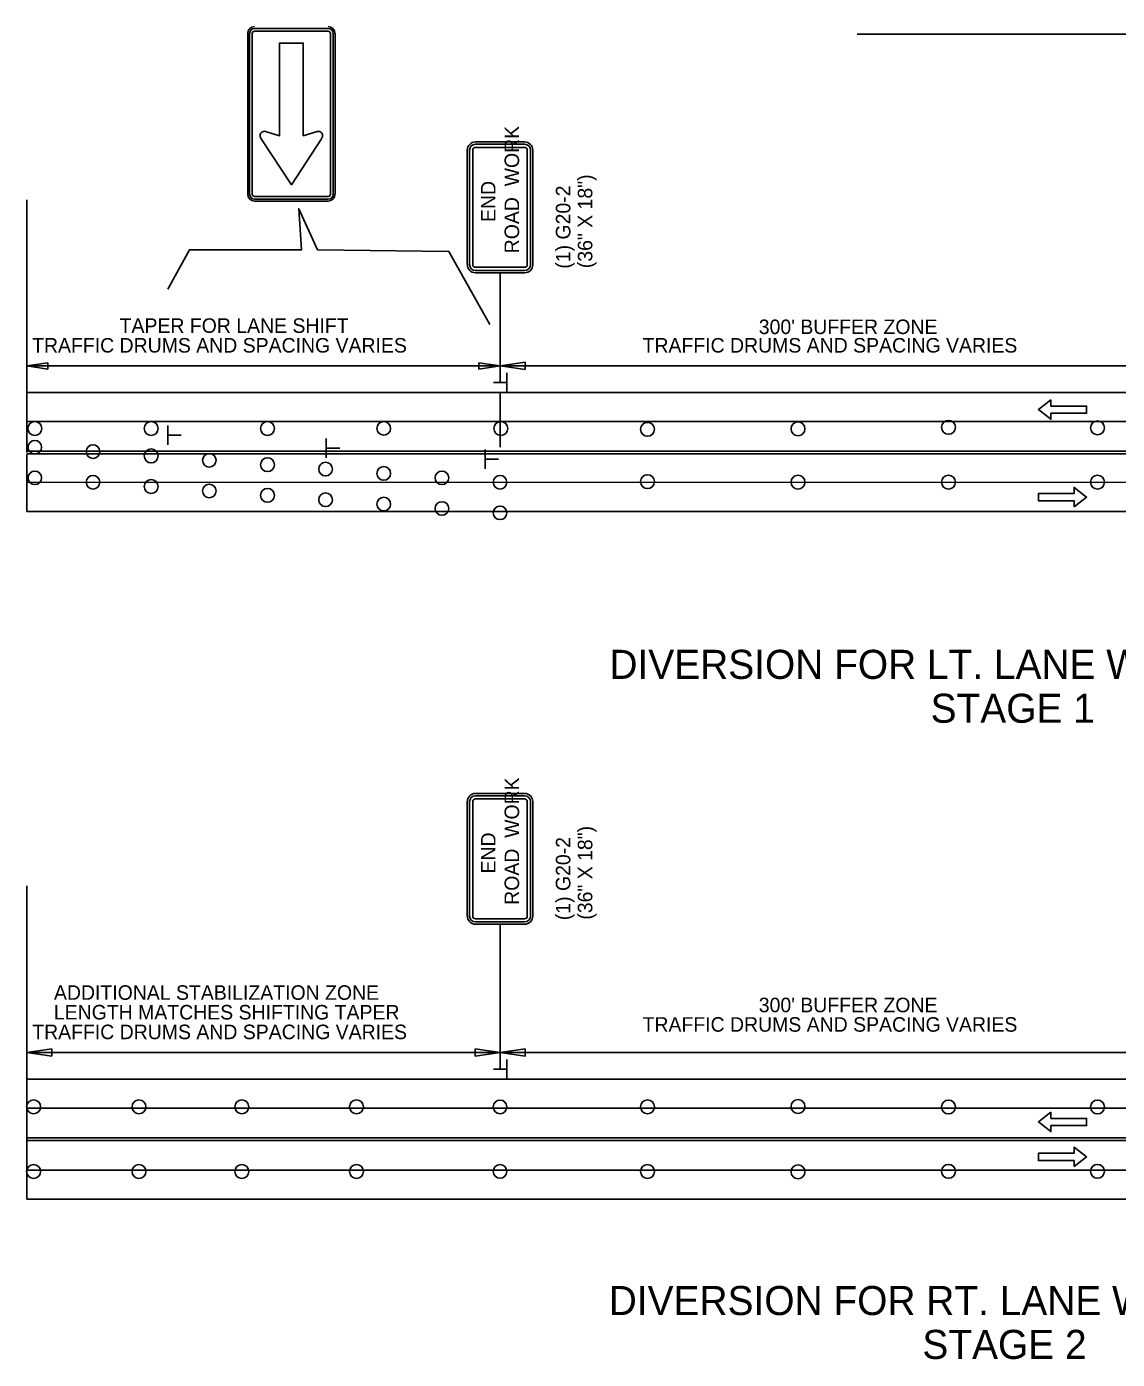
# Model space of a CAD drawing. Extents: x 1930579 to 1938013, y 596452 to 597673.
# Drawn here: x 1933682 to 1934133, y 596636 to 597187 of the extents above; entities that cross this region are included whole.
import ezdxf

# ---------------------------------------------------------------- set-up
doc = ezdxf.new("R2010")
doc.units = 0
for name, color, linetype in [('Default', 7, 'Continuous'), ('P_TC_Signs_Permanent', 7, 'Continuous'), ('P_TC_Signs_Temporary', 7, 'Continuous'), ('R_Annotation', 7, 'Continuous'), ('R_Striping', 7, 'Continuous')]:
    doc.layers.add(name, color=color, linetype=linetype)

msp = doc.modelspace()

# ---------------------------------------------------------------- linework, layer by layer
at = {"layer": 'Default'}
for p, q in [((1934025.15, 597183.38), (1934153.46, 597183.38)), ((1933682.42, 597114.97), (1933682.42, 597010.74)), ((1933877.75, 597057.24), (1933877.75, 597041.13)), ((1933682.42, 597046.45), (1933691.12, 597047.75)), ((1933691.12, 597047.75), (1933691.12, 597045.15)), ((1933869.06, 597045.15), (1933869.06, 597047.75)), ((1933869.06, 597047.75), (1933877.75, 597046.45)), ((1933877.84, 597046.45), (1933888.14, 597048)), ((1933888.14, 597048), (1933888.14, 597044.9)), ((1933877.75, 597046.45), (1933682.42, 597046.45)), ((1933691.12, 597045.15), (1933682.42, 597046.45)), ((1933877.75, 597046.45), (1933869.06, 597045.15)), ((1934186.36, 597046.45), (1933877.75, 597046.45)), ((1933888.14, 597044.9), (1933877.84, 597046.45)), ((1933880.6, 597043.56), (1933880.6, 597035.58)), ((1933880.48, 597039.59), (1933875.03, 597039.59)), ((1934686.11, 597035.46), (1933682.42, 597035.46)), ((1933877.75, 597035.77), (1933877.75, 597012.95)), ((1933682.42, 597023.46), (1934686.11, 597023.46)), ((1933740.62, 597013.87), (1933740.62, 597021.85)), ((1933740.74, 597017.84), (1933746.18, 597017.84)), ((1933806.03, 597008.46), (1933806.03, 597016.44)), ((1934686.11, 597011.23), (1933682.42, 597011.23)), ((1934686.11, 597010.08), (1933682.42, 597010.08)), ((1933682.42, 597009.88), (1933682.42, 596986.31)), ((1933806.15, 597012.42), (1933811.6, 597012.42)), ((1933871.6, 597003.94), (1933871.6, 597011.92)), ((1933871.71, 597007.91), (1933877.16, 597007.91)), ((1933682.42, 596998.31), (1934686.11, 596998.53)), ((1933682.42, 596986.31), (1933962.94, 596986.31)), ((1934686.11, 596986.31), (1933682.42, 596986.31)), ((1933947.06, 596986.31), (1934222.13, 596986.31)), ((1933682.42, 596831.73), (1933682.42, 596726.82)), ((1933877.75, 596773.75), (1933877.75, 596757.64)), ((1933682.42, 596762.96), (1933692.73, 596764.51)), ((1933877.84, 596762.96), (1933682.42, 596762.96)), ((1933692.73, 596761.41), (1933682.42, 596762.96)), ((1933692.73, 596764.51), (1933692.73, 596761.41)), ((1933867.54, 596761.41), (1933867.54, 596764.51)), ((1933867.54, 596764.51), (1933877.84, 596762.96)), ((1933877.84, 596762.96), (1933867.54, 596761.41)), ((1934186.36, 596762.96), (1933877.75, 596762.96)), ((1933877.84, 596762.96), (1933888.14, 596764.51)), ((1933888.14, 596761.41), (1933877.84, 596762.96)), ((1933888.14, 596764.51), (1933888.14, 596761.41)), ((1933880.48, 596756.1), (1933875.03, 596756.1)), ((1933880.6, 596760.07), (1933880.6, 596752.09)), ((1934686.11, 596751.97), (1933682.42, 596751.97)), ((1933682.42, 596739.97), (1934686.11, 596739.97)), ((1934686.11, 596727.74), (1933682.42, 596727.74)), ((1933682.42, 596726.82), (1933682.42, 596702.39)), ((1934686.11, 596726.59), (1933682.42, 596726.59)), ((1933682.42, 596714.39), (1934686.11, 596714.39)), ((1934686.11, 596702.39), (1933682.42, 596702.39)), ((1933877.75, 596702.39), (1933962.94, 596702.39)), ((1933947.06, 596702.39), (1934222.13, 596702.39))]:
    msp.add_line(p, q, dxfattribs=at)
for centre, radius in [((1933685.74, 597020.59), 2.87), ((1933733.75, 597020.59), 2.87), ((1933781.75, 597020.59), 2.87), ((1933829.75, 597020.65), 2.81), ((1933878.08, 597020.59), 2.87), ((1933938.61, 597020.27), 2.87), ((1934000.75, 597020.48), 2.87), ((1934062.89, 597021.09), 2.87), ((1934124.37, 597020.86), 2.87), ((1933685.74, 597012.89), 2.81), ((1933709.75, 597011.08), 2.81), ((1933733.75, 597009.27), 2.87), ((1933757.75, 597007.46), 2.81), ((1933781.75, 597005.65), 2.87), ((1933685.74, 597000.24), 2.81), ((1933805.75, 597003.84), 2.81), ((1933829.75, 597002.04), 2.81), ((1933853.75, 597000.23), 2.81), ((1933709.75, 596998.43), 2.81), ((1933733.75, 596996.62), 2.87), ((1933757.75, 596994.81), 2.81), ((1933877.75, 596998.42), 2.81), ((1933938.61, 596998.65), 2.87), ((1934000.75, 596998.42), 2.87), ((1934062.89, 596998.42), 2.87), ((1934124.37, 596998.42), 2.87), ((1933781.75, 596993), 2.87), ((1933805.75, 596991.19), 2.81), ((1933829.75, 596989.39), 2.81), ((1933853.75, 596987.58), 2.81), ((1933877.75, 596985.77), 2.81), ((1933685.23, 596740.51), 2.87), ((1933728.72, 596740.51), 2.87), ((1933771.19, 596740.51), 2.87), ((1933818.54, 596740.51), 2.87), ((1933877.75, 596740.51), 2.81), ((1933938.61, 596740.51), 2.87), ((1934000.75, 596740.66), 2.87), ((1934062.89, 596740.45), 2.87), ((1934124.37, 596740.44), 2.87), ((1934124.37, 596713.91), 2.87), ((1933685.23, 596713.84), 2.87), ((1933728.72, 596713.84), 2.87), ((1933771.19, 596713.84), 2.87), ((1933818.54, 596713.84), 2.87), ((1933877.75, 596713.84), 2.81), ((1933938.61, 596713.84), 2.87), ((1934000.75, 596713.69), 2.87), ((1934062.89, 596713.9), 2.87)]:
    msp.add_circle(centre, radius, dxfattribs=at)
at = {"layer": 'P_TC_Signs_Permanent'}
for p, q in [((1933806.82, 597185.77), (1933776.45, 597185.77)), ((1933806.82, 597184.65), (1933776.45, 597184.65)), ((1933773.64, 597183.71), (1933773.64, 597117.33)), ((1933774.39, 597183.71), (1933774.39, 597117.33)), ((1933775.51, 597183.71), (1933775.51, 597117.33)), ((1933807.76, 597117.33), (1933807.76, 597183.71)), ((1933808.89, 597117.33), (1933808.89, 597183.71)), ((1933809.64, 597117.33), (1933809.64, 597183.71)), ((1933776.45, 597116.4), (1933806.82, 597116.4)), ((1933776.45, 597115.27), (1933806.82, 597115.27)), ((1933776.45, 597114.52), (1933806.82, 597114.52))]:
    msp.add_line(p, q, dxfattribs=at)
for points in [[(1933802.27, 597143.22), (1933796.51, 597141.5), (1933796.51, 597179.77), (1933786.76, 597179.77), (1933786.76, 597141.5), (1933781.01, 597143.26)], [(1933779.19, 597140.26), (1933791.64, 597121.27), (1933804.04, 597140.27)]]:
    msp.add_lwpolyline(points, dxfattribs=at)
for centre, radius, start, end in [((1933776.45, 597183.71), 2.81, 90, 180), ((1933776.45, 597183.71), 2.06, 90, 180), ((1933776.45, 597183.71), 0.938, 90, 180), ((1933806.82, 597183.71), 2.81, 360, 90), ((1933806.82, 597183.71), 2.06, 360, 90), ((1933806.82, 597183.71), 0.937, 360, 90), ((1933780.52, 597141.53), 1.8, 74.0309, 213.4755), ((1933716.46, 597099.16), 75, 33.2286, 33.4755), ((1933802.75, 597141.53), 1.76, 326.5994, 105.9691), ((1933866.84, 597099.27), 75, 146.5994, 146.857), ((1933776.45, 597117.33), 2.81, 180, 270), ((1933776.45, 597117.33), 2.06, 180, 270), ((1933776.45, 597117.33), 0.938, 180, 270), ((1933806.82, 597117.33), 2.81, 270, 360), ((1933806.82, 597117.33), 2.06, 270, 360), ((1933806.82, 597117.33), 0.938, 270, 360)]:
    msp.add_arc(centre, radius, start, end, dxfattribs=at)
at = {"layer": 'P_TC_Signs_Temporary'}
for p, q in [((1933864.25, 597135.53), (1933864.25, 597088.28)), ((1933865.19, 597135.53), (1933865.19, 597088.28)), ((1933866.5, 597135.53), (1933866.5, 597088.28)), ((1933887.88, 597138.91), (1933867.63, 597138.91)), ((1933887.88, 597137.97), (1933867.63, 597137.97)), ((1933887.88, 597136.66), (1933867.63, 597136.66)), ((1933889, 597088.28), (1933889, 597135.53)), ((1933890.32, 597088.28), (1933890.32, 597135.53)), ((1933891.25, 597088.28), (1933891.25, 597135.53)), ((1933867.63, 597087.16), (1933887.88, 597087.16)), ((1933867.63, 597085.85), (1933887.88, 597085.85)), ((1933867.63, 597084.91), (1933887.88, 597084.91)), ((1933864.25, 596866.53), (1933864.25, 596819.28)), ((1933865.19, 596866.53), (1933865.19, 596819.28)), ((1933866.5, 596866.53), (1933866.5, 596819.28)), ((1933887.88, 596869.9), (1933867.63, 596869.9)), ((1933887.88, 596868.97), (1933867.63, 596868.97)), ((1933887.88, 596867.65), (1933867.63, 596867.65)), ((1933889, 596819.28), (1933889, 596866.53)), ((1933890.32, 596819.28), (1933890.32, 596866.53)), ((1933891.25, 596819.28), (1933891.25, 596866.53)), ((1933867.63, 596818.15), (1933887.88, 596818.15)), ((1933867.63, 596816.84), (1933887.88, 596816.84)), ((1933867.63, 596815.9), (1933887.88, 596815.9))]:
    msp.add_line(p, q, dxfattribs=at)
for centre, radius, start, end in [((1933867.63, 597135.53), 3.38, 90, 180), ((1933867.63, 597135.53), 2.44, 90, 180), ((1933867.63, 597135.53), 1.13, 90, 180), ((1933887.88, 597135.53), 3.37, 360, 90), ((1933887.88, 597135.53), 2.44, 360, 90), ((1933887.88, 597135.53), 1.13, 360, 90), ((1933867.63, 597088.28), 3.37, 180, 270), ((1933867.63, 597088.28), 2.44, 180, 270), ((1933867.63, 597088.28), 1.13, 180, 270), ((1933887.88, 597088.28), 2.44, 270, 360), ((1933887.88, 597088.28), 1.13, 270, 360), ((1933887.88, 597088.28), 3.38, 270, 360), ((1933867.63, 596866.53), 3.38, 90, 180), ((1933867.63, 596866.53), 2.44, 90, 180), ((1933867.63, 596866.53), 1.13, 90, 180), ((1933887.88, 596866.53), 3.37, 360, 90), ((1933887.88, 596866.53), 2.44, 360, 90), ((1933887.88, 596866.53), 1.13, 360, 90), ((1933867.63, 596819.28), 3.37, 180, 270), ((1933867.63, 596819.28), 2.44, 180, 270), ((1933867.63, 596819.28), 1.13, 180, 270), ((1933887.88, 596819.28), 2.44, 270, 360), ((1933887.88, 596819.28), 1.13, 270, 360), ((1933887.88, 596819.28), 3.38, 270, 360)]:
    msp.add_arc(centre, radius, start, end, dxfattribs=at)
at = {"layer": 'R_Annotation'}
for p, q in [((1933877.75, 597084.91), (1933877.75, 597039.75)), ((1933877.75, 596815.9), (1933877.75, 596756.1))]:
    msp.add_line(p, q, dxfattribs=at)
msp.add_lwpolyline([(1933740.62, 597078.12), (1933749.63, 597094.42), (1933795.86, 597094.42), (1933794.66, 597111.31), (1933802.46, 597094.42), (1933856.66, 597093.63), (1933873.54, 597063.48)], dxfattribs=at)
at = {"layer": 'R_Striping'}
for points in [[(1934105.16, 597032.39), (1934099.97, 597028.39), (1934105.16, 597024.39), (1934105.16, 597026.89), (1934119.87, 597026.89), (1934119.87, 597029.89), (1934105.16, 597029.89)], [(1934114.68, 596988.26), (1934119.87, 596992.26), (1934114.68, 596996.26), (1934114.68, 596993.76), (1934099.97, 596993.76), (1934099.97, 596990.76), (1934114.68, 596990.76)], [(1934105.16, 596738.27), (1934099.97, 596734.27), (1934105.16, 596730.27), (1934105.16, 596732.77), (1934119.87, 596732.77), (1934119.87, 596735.77), (1934105.16, 596735.77)], [(1934114.68, 596715.86), (1934119.87, 596719.86), (1934114.68, 596723.86), (1934114.68, 596721.36), (1934099.97, 596721.36), (1934099.97, 596718.36), (1934114.68, 596718.36)]]:
    msp.add_lwpolyline(points, close=True, dxfattribs=at)

# ---------------------------------------------------------------- texts
at = {"layer": 'Default'}
for s, height, p in [('TAPER FOR LANE SHIFT', 6, (1933720.74, 597060.08)), ("300' BUFFER ZONE", 6, (1933984.55, 597059.59)), ('TRAFFIC DRUMS AND SPACING VARIES', 6, (1933684.61, 597051.95)), ('TRAFFIC DRUMS AND SPACING VARIES', 6, (1933936.58, 597051.95)), ('DIVERSION FOR LT. LANE WORK ZONE', 12, (1933922.91, 596917.22)), ('STAGE 1', 12, (1934055.48, 596899.1)), ('ADDITIONAL STABILIZATION ZONE', 6, (1933693.63, 596784.71)), ("300' BUFFER ZONE", 6, (1933984.55, 596779.58)), ('LENGTH MATCHES SHIFTING TAPER', 6, (1933693.6, 596776.59)), ('TRAFFIC DRUMS AND SPACING VARIES', 6, (1933936.58, 596771.54)), ('TRAFFIC DRUMS AND SPACING VARIES', 6, (1933684.66, 596768.46)), ('DIVERSION FOR RT. LANE WORK ZONE', 12, (1933922.63, 596654.55)), ('STAGE 2', 12, (1934052.08, 596636.43))]:
    msp.add_text(s, height=height, rotation=360, dxfattribs=at).set_placement(p)
at = {"layer": 'P_TC_Signs_Temporary'}
for s, p in [('ROAD  WORK', (1933885.63, 597092.95)), ('END', (1933875.88, 597105.88)), ('ROAD  WORK', (1933885.63, 596823.94)), ('END', (1933875.88, 596836.87))]:
    msp.add_text(s, height=6, rotation=90, dxfattribs=at).set_placement(p)
at = {"layer": 'R_Annotation'}
for s, p in [('(36" X 18")', (1933915.85, 597086.8)), ('(1) G20-2', (1933906.79, 597086.59)), ('(36" X 18")', (1933915.85, 596817.8)), ('(1) G20-2', (1933906.79, 596817.59))]:
    msp.add_text(s, height=6, rotation=90, dxfattribs=at).set_placement(p)

doc.saveas('drawing.dxf')
